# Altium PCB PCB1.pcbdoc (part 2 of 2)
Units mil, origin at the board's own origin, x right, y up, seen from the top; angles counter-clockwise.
Board outline 1855 x 1070 mil, 2 copper layers (Top Layer, Bottom Layer), stack 62.206 mil thick; 23 components, 23 nets, 105 pads, 33 vias.
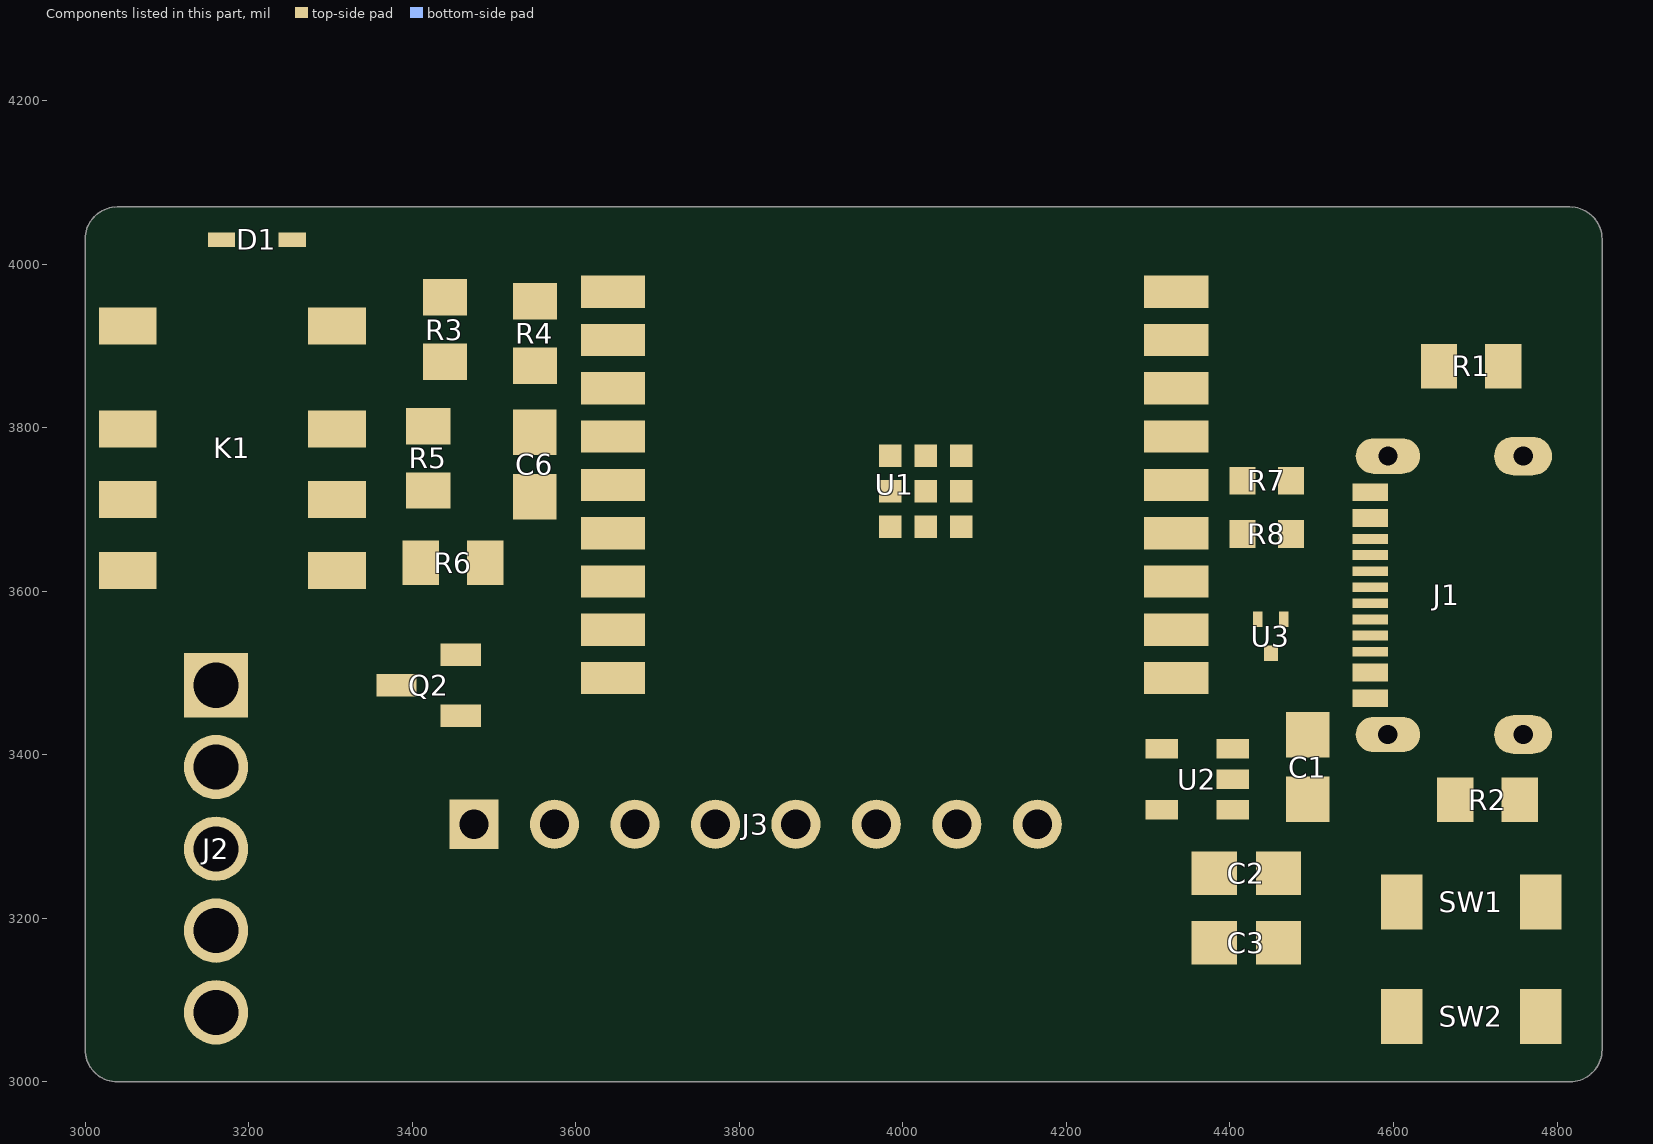
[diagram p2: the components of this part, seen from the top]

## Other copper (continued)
Bottom Layer:
  region net GND: 3933.19,3338.31 3944.33,3349.45 3945.53,3348.42 3946.91,3347.56 3948.42,3346.85 3950.05,3346.28 3953.56,3345.5 3957.23,3345.09 3960.87,3344.94 3964.26,3344.95 3969.52,3344.94 3937.7,3313.12 3937.69,3318.38 3937.7,3321.77 3937.55,3325.41 3937.14,3329.08 3936.36,3332.59 3935.79,3334.22 3935.08,3335.73 3934.22,3337.11
  region net GND: 3960.66,3354.32 3970.66,3357.28 3970.82,3355.7 3971.28,3354.13 3972,3352.56 3972.94,3351.01 3975.36,3347.98 3978.25,3345.1 3981.32,3342.43 3984.29,3340.03 3986.88,3337.96 3988.78,3336.28 3943.88,3333.32 3945.55,3335.1 3947.89,3337.21 3953.5,3342.26 3956.22,3345.1 3958.5,3348.09 3959.4,3349.63 3960.08,3351.18 3960.51,3352.74
  region net RST: 4185.28,3340 4215.34,3330 4213.73,3329.86 4212.05,3329.45 4210.33,3328.81 4208.59,3327.97 4205.15,3325.76 4201.9,3323.08 4199.01,3320.13 4196.67,3317.16 4195.06,3314.38 4194.58,3313.14 4194.34,3312.03 4164.28,3345 4166.08,3344.79 4168.2,3344.23 4173.25,3342.51 4176.08,3341.59 4179.06,3340.79 4182.14,3340.22
  region net GPIO2: 4253.65,3845 4253.65,3855 4255.46,3855.34 4257.73,3856.25 4260.06,3857.53 4262.06,3859.01 4262.06,3840.99 4260.06,3842.47 4257.73,3843.75 4255.46,3844.66
  region net GPIO2: 3493.02,3835.1 3500.1,3828.02 3499.06,3826.5 3498.1,3824.26 3497.36,3821.7 3496.98,3819.25 3484.25,3831.98 3486.7,3832.36 3489.26,3833.1 3491.5,3834.06
  region net RST: 4261.98,3539.9 4254.9,3546.98 4255.94,3548.5 4256.9,3550.74 4257.64,3553.3 4258.02,3555.75 4270.75,3543.02 4268.3,3542.64 4265.74,3541.9 4263.5,3540.94
  region net $1N27: 4610,3647.56 4600,3647.56 4599.66,3649.37 4598.75,3651.63 4597.47,3653.96 4595.99,3655.96 4614.01,3655.96 4612.53,3653.96 4611.25,3651.63 4610.34,3649.37
  region net $1N27: 4613.65,3340 4613.65,3350 4615.46,3350.34 4617.73,3351.25 4620.06,3352.53 4622.06,3354.01 4622.06,3335.99 4620.06,3337.47 4617.73,3338.75 4615.46,3339.66
  region net GND: 3552.87,3648.65 3537.13,3648.65 3537.03,3651.38 3536.77,3653.95 3536.41,3655.97 3535.99,3657.06 3554.01,3657.06 3553.59,3655.97 3553.23,3653.95 3552.97,3651.38
  region net 3V3: 3854.8,3255.16 3854.8,3274.84 3856.95,3274.94 3859.07,3275.18 3863.07,3275.93 3866.54,3276.67 3869.21,3277.01 3869.21,3252.99 3866.54,3253.33 3863.07,3254.07 3859.07,3254.82 3856.95,3255.06
  region net 3V3: 3361.22,3937.3 3347.3,3951.22 3348.75,3952.81 3350.08,3954.48 3352.38,3957.83 3354.31,3960.81 3355.95,3962.94 3372.94,3945.95 3370.81,3944.31 3367.83,3942.38 3364.48,3940.08 3362.81,3938.75
  region net GND: 3475.72,3582.87 3475.72,3567.13 3472.99,3567.03 3470.42,3566.77 3468.4,3566.41 3467.31,3565.99 3467.31,3584.01 3468.4,3583.59 3470.42,3583.23 3472.99,3582.97
  region net GND: 3531.18,3567.13 3522.89,3582.87 3525.86,3582.93 3528.5,3583.12 3530.44,3583.46 3531.02,3583.69 3531.29,3583.97 3539.58,3568.72 3538.88,3568.78 3538.04,3568.66 3536.02,3568.09 3533.67,3567.44 3532.43,3567.21
  region net GND: 3547.87,3562.12 3532.13,3566.21 3532.24,3568.73 3532.44,3571.12 3532.49,3573.15 3532.38,3573.97 3532.15,3574.62 3549.69,3570.52 3549.35,3570.12 3549.03,3569.44 3548.44,3567.41 3548.03,3564.84
  region net GND: 3537.13,3598.21 3552.87,3594.8 3552.81,3589.36 3552.86,3587.45 3553.07,3586.4 3535.39,3589.81 3535.71,3590.22 3536.03,3590.91 3536.58,3592.94 3536.98,3595.5
  region net MOSI: 3700,3654.6 3690,3654.6 3689.66,3656.41 3688.75,3658.68 3687.47,3661.01 3685.99,3663.01 3704.01,3663.01 3702.53,3661.01 3701.25,3658.68 3700.34,3656.41
  region net SS: 3711.35,3735 3711.35,3725 3709.54,3724.66 3707.27,3723.75 3704.94,3722.47 3702.94,3720.99 3702.94,3739.01 3704.94,3737.53 3707.27,3736.25 3709.54,3735.34
  region net MOSI: 3690,3416.35 3700,3416.35 3700.34,3414.54 3701.25,3412.27 3702.53,3409.94 3704.01,3407.94 3685.99,3407.94 3687.47,3409.94 3688.75,3412.27 3689.66,3414.54
  region net SS: 3765.79,3416.35 3775.79,3416.35 3776.13,3414.54 3777.04,3412.27 3778.32,3409.94 3779.8,3407.94 3761.78,3407.94 3763.26,3409.94 3764.54,3412.27 3765.45,3414.54
  region net $1N24: 3725,3536.49 3715,3536.49 3714.66,3538.3 3713.75,3540.57 3712.47,3542.9 3710.99,3544.9 3729.01,3544.9 3727.53,3542.9 3726.25,3540.57 3725.34,3538.3
  region net $1N24: 3715,3410.3 3725,3425.37 3725.09,3423.74 3725.34,3422.18 3725.73,3420.74 3726.23,3419.45 3726.82,3418.39 3727.49,3417.58 3728.2,3417.09 3728.93,3416.96 3718.4,3401.9 3717.67,3403.48 3716.52,3405.5 3715.47,3407.82 3715.13,3409.05
  region net $1N24: 3390,3848.65 3380,3848.65 3379.66,3850.46 3378.75,3852.73 3377.47,3855.06 3375.99,3857.06 3394.01,3857.06 3392.53,3855.06 3391.25,3852.73 3390.34,3850.46
  region net $1N24: 3566.56,3556.37 3573.63,3563.44 3575.15,3562.41 3577.39,3561.45 3579.95,3560.71 3582.4,3560.33 3569.67,3547.6 3569.29,3550.05 3568.55,3552.61 3567.59,3554.85
  region net $1N15: 4010.79,3410.56 4010.79,3400.56 4008.98,3400.22 4006.71,3399.31 4004.38,3398.03 4002.38,3396.55 4002.38,3414.57 4004.38,3413.1 4006.71,3411.81 4008.98,3410.91
  region net $1N15: 4603.23,3156.16 4596.16,3163.23 4597.2,3164.76 4598.16,3167 4598.9,3169.56 4599.27,3172.01 4612.01,3159.27 4609.56,3158.9 4607,3158.16 4604.76,3157.2
  region net GND: 3578.65,3490 3578.65,3500 3580.46,3500.34 3582.73,3501.25 3585.06,3502.53 3587.06,3504.01 3587.06,3485.99 3585.06,3487.47 3582.73,3488.75 3580.46,3489.66
  region net GND: 3970.66,3643.65 3960.66,3643.65 3960.32,3645.45 3959.41,3647.72 3958.13,3650.05 3956.66,3652.05 3974.67,3652.05 3973.2,3650.05 3971.92,3647.72 3971.01,3645.45
  region net +5V: 4407.52,3445.44 4417.71,3441.5 4417.05,3440.69 4416.46,3439.67 4415.53,3437.22 4415.04,3434.59 4415,3433.34 4415.11,3432.21 4399.64,3441.43 4401.92,3442.29 4404.23,3443.37 4406.22,3444.49
  region net +5V: 4516.98,3679.9 4509.9,3686.98 4510.94,3688.5 4511.9,3690.74 4512.64,3693.3 4513.02,3695.75 4525.75,3683.02 4523.3,3682.64 4520.74,3681.9 4518.5,3680.94
  region net $1N26: 4633.19,3816.81 4633.19,3806.81 4632.79,3806.65 4632.41,3806.21 4631.69,3804.84 4631.04,3803.3 4630.49,3802.24 4627.39,3819.98 4631.01,3817.8 4632.37,3817.08
  region net GND: 3595,3500 cw(c3595,3568.94) 3547.87,3518.62 3540,3495.86 3547.87,3471.38 cw(c3595,3421.06) 3595,3490
  region net $1N26: 4623.02,3560.89 4630.1,3553.82 4629.06,3552.3 4628.1,3550.05 4627.36,3547.5 4626.98,3545.04 4614.25,3557.78 4616.7,3558.15 4619.26,3558.89 4621.5,3559.85
  region net +5V: 4696.63,3726.35 4706.63,3726.35 4706.97,3724.54 4707.88,3722.27 4709.16,3719.94 4710.63,3717.94 4692.62,3717.94 4694.09,3719.94 4695.38,3722.27 4696.28,3724.54
  region net +5V: 4536.35,3855 4536.35,3845 4534.54,3844.66 4532.27,3843.75 4529.94,3842.47 4527.94,3840.99 4527.94,3859.01 4529.94,3857.53 4532.27,3856.25 4534.54,3855.34
  region net GND: 4433.65,3535 4433.65,3545 4435.46,3545.34 4437.73,3546.25 4440.06,3547.53 4442.06,3549.01 4442.06,3530.99 4440.06,3532.47 4437.73,3533.75 4435.46,3534.66
  region net GND: 4390,3491.35 4400,3491.35 4400.34,3489.54 4401.25,3487.27 4402.53,3484.94 4404.01,3482.94 4385.99,3482.94 4387.47,3484.94 4388.75,3487.27 4389.66,3489.54
  region net +5V: 4503.42,3992.66 4517.34,4006.58 4518.93,4005.12 4520.6,4003.79 4523.96,4001.49 4526.94,3999.57 4529.06,3997.92 4512.08,3980.94 4510.43,3983.06 4508.51,3986.04 4506.21,3989.4 4504.88,3991.07
  region net +5V: 3114.29,3086.79 3105.71,3123.21 3107.32,3121.84 3109.21,3120.67 3111.32,3119.67 3113.63,3118.85 3116.08,3118.19 3118.64,3117.68 3123.91,3117.11 3129.1,3117.06 3133.89,3117.48 3137.94,3118.29 3139.58,3118.82 3140.91,3119.43 3128.23,3061.75 3126.98,3063.84 3125.72,3066.52 3122.91,3073.08 3121.23,3076.66 3119.28,3080.24 3116.99,3083.67 3115.7,3085.27
  region net +5V: 3134.84,3915.59 3115.16,3915.59 3115.06,3917.74 3114.82,3919.86 3114.07,3923.86 3113.33,3927.33 3112.99,3930 3137.01,3930 3136.67,3927.33 3135.93,3923.86 3135.18,3919.86 3134.94,3917.74
  region net +5V: 3115.16,3944.41 3134.84,3944.41 3134.94,3942.26 3135.18,3940.14 3135.93,3936.14 3136.67,3932.67 3137.01,3930 3112.99,3930 3113.33,3932.67 3114.07,3936.14 3114.82,3940.14 3115.06,3942.26
  region net GND: 3958.63,3125.94 3978.31,3125.94 3978.4,3123.79 3978.65,3121.67 3979.39,3117.67 3980.14,3114.2 3980.48,3111.53 3956.46,3111.53 3956.8,3114.2 3957.54,3117.67 3958.29,3121.67 3958.53,3123.79
  region net GND: 3978.31,3274.79 3958.63,3273.54 3958.52,3275.12 3958.21,3276.71 3957.72,3278.29 3957.08,3279.86 3955.42,3282.93 3953.42,3285.84 3951.26,3288.53 3949.14,3290.92 3945.7,3294.54 3990.68,3295.79 3987.43,3292.11 3985.39,3289.71 3983.32,3287.03 3981.4,3284.13 3979.8,3281.08 3979.18,3279.52 3978.71,3277.95 3978.41,3276.36
  region net GND: 3204.86,3154.06 3190.94,3140.14 3189.36,3141.48 3187.54,3142.6 3185.54,3143.51 3183.38,3144.24 3181.1,3144.8 3178.73,3145.21 3173.85,3145.69 3169.02,3145.81 3164.51,3145.75 3160.59,3145.67 3157.53,3145.71 3199.29,3187.47 3199.33,3184.41 3199.25,3180.49 3199.19,3175.98 3199.31,3171.15 3199.79,3166.27 3200.2,3163.9 3200.76,3161.62 3201.49,3159.46 3202.4,3157.46 3203.52,3155.64
  region net GND: 4768.35,3371.58 4748.66,3371.58 4748.82,3376.24 4749.19,3381.17 4749.9,3390.77 4749.92,3394.87 4749.77,3396.63 4749.5,3398.15 4749.07,3399.39 4748.48,3400.32 4747.69,3400.9 4746.69,3401.1 4770.32,3401.1 4769.32,3400.9 4768.53,3400.32 4767.94,3399.39 4767.51,3398.15 4767.24,3396.63 4767.09,3394.87 4767.11,3390.77 4767.82,3381.17 4768.19,3376.24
